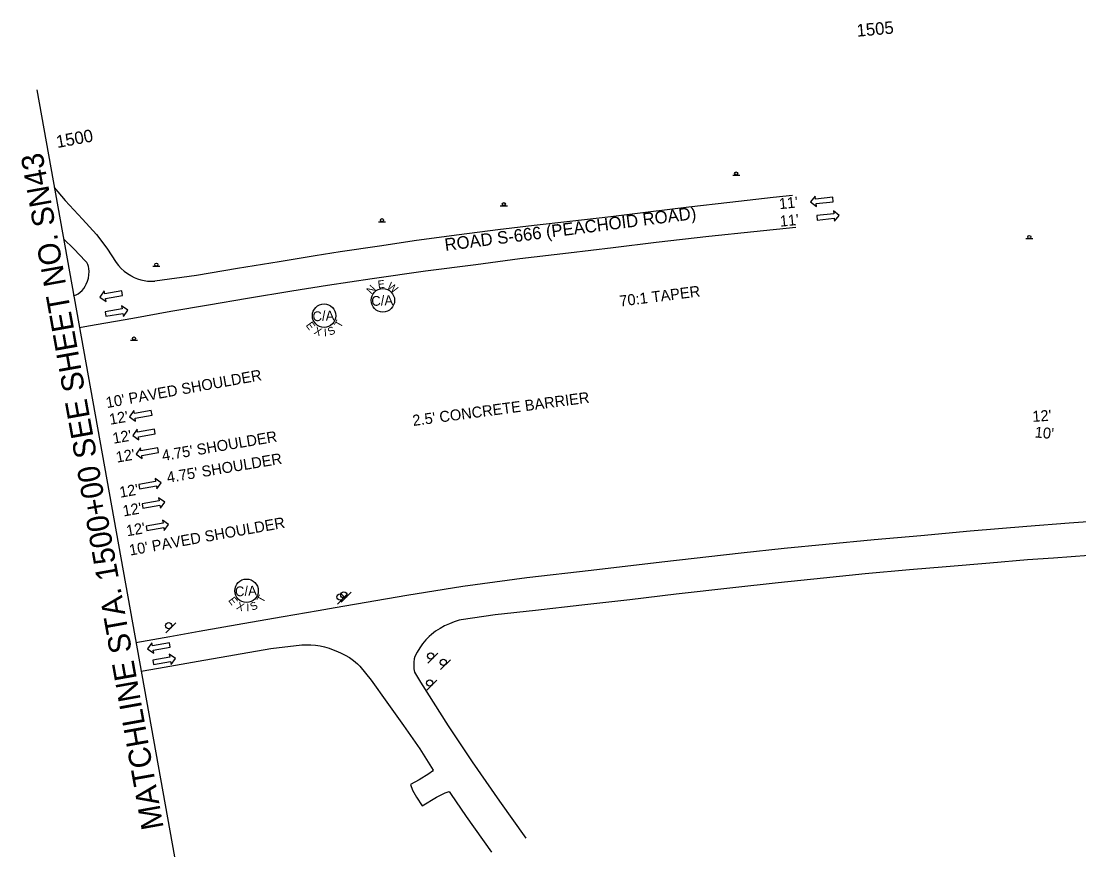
# Model space of a CAD drawing. Extents: x 1797370 to 1798969, y 1187875 to 1188793.
# Drawn here: x 1797370 to 1798047, y 1187997 to 1188532 of the extents above; entities that cross this region are included whole.
import ezdxf

# ---------------------------------------------------------------- set-up
doc = ezdxf.new("R2010")
doc.units = 0
for name, color, linetype in [('RD_EX_Road', 7, 'Continuous'), ('RD_HC_Data_Rel', 7, 'Continuous'), ('RD_PD_Final_LnLine', 7, 'Continuous'), ('RD_PD_Final_TX', 7, 'Continuous'), ('RD_SHT_MatchLine', 7, 'Continuous'), ('RD_SHT_TX', 7, 'Continuous'), ('RD_Sketch10', 7, 'Continuous'), ('RD_Sketch8', 7, 'Continuous'), ('RD_TX_RoadID', 7, 'Continuous'), ('SN_P_Signs', 7, 'Continuous')]:
    doc.layers.add(name, color=color, linetype=linetype)

# ---------------------------------------------------------------- blocks, each defined once
blk = doc.blocks.new('SARRW2')
at = {"layer": 'RD_PD_Final_LnLine'}
blk.add_lwpolyline([(-12, 1.2), (-12, -1.2), (-2.83, -1.2), (-2.83, -2.83), (0, 0), (-2.83, 2.83), (-2.83, 1.2)], close=True, dxfattribs=at)

msp = doc.modelspace()

# ---------------------------------------------------------------- linework, layer by layer
at = {"layer": 'RD_EX_Road'}
for points in [[(1797391.48, 1188425.58), (1797398.52, 1188417.19), (1797409.6, 1188405.25), (1797418.44, 1188395.48), (1797425.17, 1188386.77), (1797431.03, 1188377.69), (1797432.58, 1188375.68), (1797434.31, 1188373.81), (1797436.21, 1188372.12), (1797438.25, 1188370.61), (1797440.43, 1188369.29), (1797440.8, 1188369.1), (1797442.73, 1188368.05), (1797444.74, 1188367.18), (1797446.82, 1188366.5), (1797448.95, 1188366.01), (1797451.12, 1188365.71), (1797453.3, 1188365.61), (1797455.49, 1188365.7), (1797455.78, 1188365.73)], [(1797864.01, 1188420.39), (1797851.82, 1188419.22), (1797824.03, 1188415.92), (1797797.69, 1188412.98), (1797771.74, 1188409.8), (1797747.78, 1188406.91), (1797721.63, 1188403.93), (1797698.76, 1188401.19), (1797675.37, 1188398.4), (1797650.67, 1188395.21), (1797623.28, 1188391.62), (1797599.73, 1188388.15), (1797574.44, 1188384.33), (1797558.51, 1188381.86), (1797535.45, 1188378.12), (1797508.71, 1188373.79), (1797482.47, 1188369.32), (1797455.78, 1188365.73)], [(1797407.58, 1188335.94), (1797413.34, 1188337), (1797441.67, 1188341.96), (1797466.18, 1188346.48), (1797490.26, 1188350.42), (1797515.14, 1188354.85), (1797543.52, 1188359.44), (1797566.39, 1188363.09), (1797594.97, 1188367.44), (1797629.24, 1188372.18), (1797661.28, 1188376.4), (1797689.48, 1188380.07), (1797720.65, 1188383.82), (1797749.24, 1188387.17), (1797776.89, 1188390.57), (1797810.63, 1188394.4), (1797839.35, 1188397.39), (1797866.3, 1188400.15)], [(1797403.86, 1188356.16), (1797405.39, 1188356.81), (1797406.82, 1188357.63), (1797408.14, 1188358.62), (1797409.34, 1188359.76), (1797410.39, 1188361.04), (1797411.29, 1188362.43), (1797411.91, 1188363.68), (1797412.71, 1188365.61), (1797413.29, 1188367.62), (1797413.64, 1188369.68), (1797413.75, 1188371.77), (1797413.63, 1188373.77), (1797413.41, 1188375.1), (1797412.96, 1188376.37), (1797412.3, 1188377.54), (1797411.57, 1188378.43), (1797403.9, 1188386.41), (1797397.38, 1188392.72)], [(1797443.77, 1188134.4), (1797465.53, 1188138.23), (1797484.24, 1188141.55), (1797512.09, 1188146.36), (1797537.95, 1188150.95), (1797560.34, 1188154.8), (1797571.39, 1188156.81), (1797617.25, 1188164.66), (1797652.99, 1188170.38), (1797694.08, 1188175.94), (1797735.25, 1188180.66), (1797780.37, 1188185.84), (1797831.27, 1188191.62), (1797858.72, 1188194.62), (1797885.34, 1188197.34), (1797916.43, 1188200.3), (1797946.24, 1188202.86), (1797977.79, 1188205.69), (1798014.19, 1188208.78), (1798041.19, 1188210.86), (1798065.04, 1188212.53)], [(1798053.9, 1188189.97), (1798031.14, 1188188.35), (1798014.65, 1188187.18), (1797990.37, 1188185), (1797962.46, 1188182.64), (1797939.03, 1188180.72), (1797910.55, 1188178.18), (1797883.87, 1188175.46), (1797854.95, 1188172.46), (1797825.9, 1188169.22), (1797789.64, 1188165.19), (1797759.93, 1188161.65), (1797729.19, 1188158.12), (1797699.57, 1188154.81), (1797673.79, 1188152.06), (1797651.91, 1188148.81), (1797650.79, 1188148.53), (1797647.57, 1188147.55), (1797644.43, 1188146.35), (1797641.38, 1188144.94), (1797638.44, 1188143.31), (1797635.62, 1188141.48), (1797632.93, 1188139.46), (1797631.55, 1188138.2), (1797629.34, 1188135.93), (1797627.31, 1188133.5), (1797625.46, 1188130.92), (1797623.81, 1188128.21), (1797622.36, 1188125.39), (1797621.98, 1188123.82), (1797621.67, 1188121.7), (1797621.6, 1188119.56), (1797621.76, 1188117.42), (1797622.16, 1188115.31), (1797626.04, 1188108.85), (1797643.56, 1188080.99), (1797659.03, 1188058), (1797676.43, 1188032.77), (1797693.3, 1188009.11)], [(1797447.09, 1188115.9), (1797458.11, 1188117.85), (1797483.5, 1188122.36), (1797506.94, 1188126.38), (1797530.15, 1188130.43), (1797549.92, 1188132.72), (1797552.86, 1188132.87), (1797555.81, 1188132.82), (1797558.74, 1188132.57), (1797561.66, 1188132.13), (1797564.53, 1188131.49), (1797567.36, 1188130.67), (1797570.13, 1188129.65), (1797571.76, 1188128.95), (1797574.75, 1188127.72), (1797577.63, 1188126.28), (1797580.4, 1188124.62), (1797583.05, 1188122.77), (1797585.55, 1188120.73), (1797587.15, 1188119.24), (1797594.29, 1188110.14), (1797604.43, 1188096.06), (1797615.07, 1188081.08), (1797625.61, 1188066.23), (1797633.95, 1188052.59), (1797633.67, 1188051.88), (1797631.33, 1188050.26), (1797625.04, 1188046.28), (1797619.49, 1188043.35), (1797620.92, 1188039.74), (1797623.37, 1188035.28), (1797627, 1188029.74), (1797636.28, 1188035.32), (1797641.79, 1188038), (1797644.23, 1188038.87), (1797645.1, 1188037.71), (1797655.16, 1188022.99), (1797671.31, 1187999.99)]]:
    msp.add_lwpolyline(points, dxfattribs=at)
at = {"layer": 'RD_SHT_MatchLine'}
msp.add_line((1797380.26, 1188488.06), (1797468.43, 1187997.07), dxfattribs=at)
at = {"layer": 'RD_Sketch10'}
msp.add_circle((1797601.84, 1188353.38), 7.5, dxfattribs=at)
at = {"layer": 'RD_Sketch8'}
for centre in [(1797564.2, 1188343.54), (1797514.57, 1188167.41)]:
    msp.add_circle(centre, 7.5, dxfattribs=at)
at = {"layer": 'SN_P_Signs'}
for p, q in [((1797825.8, 1188433.59), (1797830.3, 1188433.59)), ((1797677.05, 1188413.95), (1797681.55, 1188413.95)), ((1797599.09, 1188403.7), (1797603.59, 1188403.7)), ((1798013.46, 1188392.96), (1798017.96, 1188392.96)), ((1797454.61, 1188375.15), (1797459.11, 1188375.15)), ((1797440.26, 1188327.96), (1797444.76, 1188327.96)), ((1797572.71, 1188158.84), (1797579.08, 1188165.21)), ((1797575.11, 1188160.06), (1797581.48, 1188166.43)), ((1797462.97, 1188140.5), (1797469.34, 1188146.87)), ((1797630.7, 1188121), (1797637.07, 1188127.37)), ((1797638.73, 1188116.91), (1797645.1, 1188123.27)), ((1797630.05, 1188103.74), (1797636.41, 1188110.1))]:
    msp.add_line(p, q, dxfattribs=at)
for centre, radius in [((1797828.06, 1188434.6), 1), ((1797679.31, 1188414.97), 1), ((1797601.35, 1188404.72), 1), ((1798015.72, 1188393.97), 1), ((1797456.87, 1188376.16), 1), ((1797442.52, 1188328.97), 1), ((1797574.48, 1188163.47), 2), ((1797576.88, 1188164.69), 2), ((1797464.74, 1188145.13), 2), ((1797632.46, 1188125.63), 2), ((1797640.49, 1188121.53), 2), ((1797631.81, 1188108.36), 2)]:
    msp.add_circle(centre, radius, dxfattribs=at)

# ---------------------------------------------------------------- block references
at = {"layer": 'RD_PD_Final_LnLine'}
for p, xscale, yscale, rotation in [((1797875.68, 1188416.42), 1.1999999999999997, 1.2000000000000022, -174.03629580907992), ((1797894.07, 1188407.7), 1.2, 1.2000000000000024, 5.963704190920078), ((1797420.71, 1188355.47), 1.1999999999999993, 1.2000000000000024, -170.16826744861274), ((1797438.53, 1188347.01), 1.1999999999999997, 1.200000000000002, 9.831732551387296), ((1797439.64, 1188278.85), 1.1999999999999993, 1.2000000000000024, -170.16826744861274), ((1797441.74, 1188266.9), 1.1999999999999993, 1.2000000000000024, -170.16826744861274), ((1797443.84, 1188254.95), 1.1999999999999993, 1.2000000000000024, -170.16826744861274), ((1797459.98, 1188236.58), 1.1999999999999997, 1.200000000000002, 9.831732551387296), ((1797462.16, 1188224.22), 1.1999999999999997, 1.200000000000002, 9.831732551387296), ((1797464.69, 1188209.86), 1.1999999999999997, 1.200000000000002, 9.831732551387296), ((1797451.26, 1188130.22), 1.1999999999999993, 1.2000000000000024, -170.16826744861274), ((1797469.05, 1188124.09), 1.1999999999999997, 1.200000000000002, 9.831732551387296)]:
    msp.add_blockref('SARRW2', p, dxfattribs=dict(at, xscale=xscale, yscale=yscale, rotation=rotation))

# ---------------------------------------------------------------- texts
at = {"layer": 'RD_HC_Data_Rel'}
for s, rotation, p in [('1505', 5.10369, (1797905.49, 1188522.1)), ('1500', 10.47398, (1797393.45, 1188450.84))]:
    msp.add_text(s, height=8, rotation=rotation, dxfattribs=at).set_placement(p)
at = {"layer": 'RD_PD_Final_TX'}
for s, rotation, p in [("11'", 5.78256, (1797855.78, 1188411.67)), ("11'", 5.78256, (1797856.35, 1188400.48)), ('70:1 TAPER', 7.24869, (1797753.72, 1188349.35)), ("10' PAVED SHOULDER", 10.21783, (1797425.16, 1188284.35)), ("2.5' CONCRETE BARRIER", 7.54659, (1797621.27, 1188272.9)), ("12'", 9.87727, (1797427.29, 1188273.66)), ("12'", 3.84935, (1798017.88, 1188275.52)), ("12'", 9.87727, (1797429.43, 1188261.52)), ("4.75' SHOULDER", 9.65651, (1797461.01, 1188250.45)), ("10'", 354.65568, (1798018.94, 1188265.63)), ("12'", 9.87727, (1797431.56, 1188249.39)), ("4.75' SHOULDER", 9.51293, (1797464.1, 1188236.46)), ("12'", 9.87727, (1797433.79, 1188226.96)), ("12'", 9.87727, (1797435.9, 1188214.96)), ("12'", 9.87727, (1797438.14, 1188202.27)), ("10' PAVED SHOULDER", 10.21783, (1797440.06, 1188189.9))]:
    msp.add_text(s, height=7, rotation=rotation, dxfattribs=at).set_placement(p)
at = {"layer": 'RD_SHT_TX'}
msp.add_text('MATCHLINE STA. 1500+00 SEE SHEET NO. SN43', height=14.1726, rotation=100.18265, dxfattribs=at).set_placement((1797461.57, 1188015.73))
at = {"layer": 'RD_Sketch10'}
for s, height, rotation, p in [('E', 5, 7.24709, (1797598.89, 1188360.94)), ('W', 5, 322.21665, (1797604.05, 1188361.45)), ('N', 5, 47.78381, (1797594.53, 1188356.84)), ('C/A', 6.25, 2.91404, (1797594.61, 1188349.73))]:
    msp.add_text(s, height=height, rotation=rotation, dxfattribs=at).set_placement(p)
at = {"layer": 'RD_Sketch8'}
for s, height, rotation, p in [('C/A', 6.25, 2.91404, (1797556.96, 1188339.89)), ('E', 5, 306.12528, (1797552.27, 1188337.4)), ('T', 5, 61.09918, (1797574.82, 1188335.36)), ('X', 5, 338.55465, (1797557.33, 1188332)), ('I', 5, 2.71465, (1797564.21, 1188330.27)), ('S', 5, 24.70648, (1797567.85, 1188330.63)), ('C/A', 6.25, 2.91404, (1797507.33, 1188163.76)), ('E', 5, 306.12528, (1797502.64, 1188161.27)), ('T', 5, 61.09918, (1797525.19, 1188159.23)), ('X', 5, 338.55465, (1797507.7, 1188155.87)), ('I', 5, 2.71465, (1797514.58, 1188154.14)), ('S', 5, 24.70648, (1797518.22, 1188154.5))]:
    msp.add_text(s, height=height, rotation=rotation, dxfattribs=at).set_placement(p)
at = {"layer": 'RD_TX_RoadID'}
msp.add_text('ROAD S-666 (PEACHOID ROAD)', height=8, rotation=7.27694, dxfattribs=at).set_placement((1797641.9, 1188384.95))

doc.saveas('drawing.dxf')
